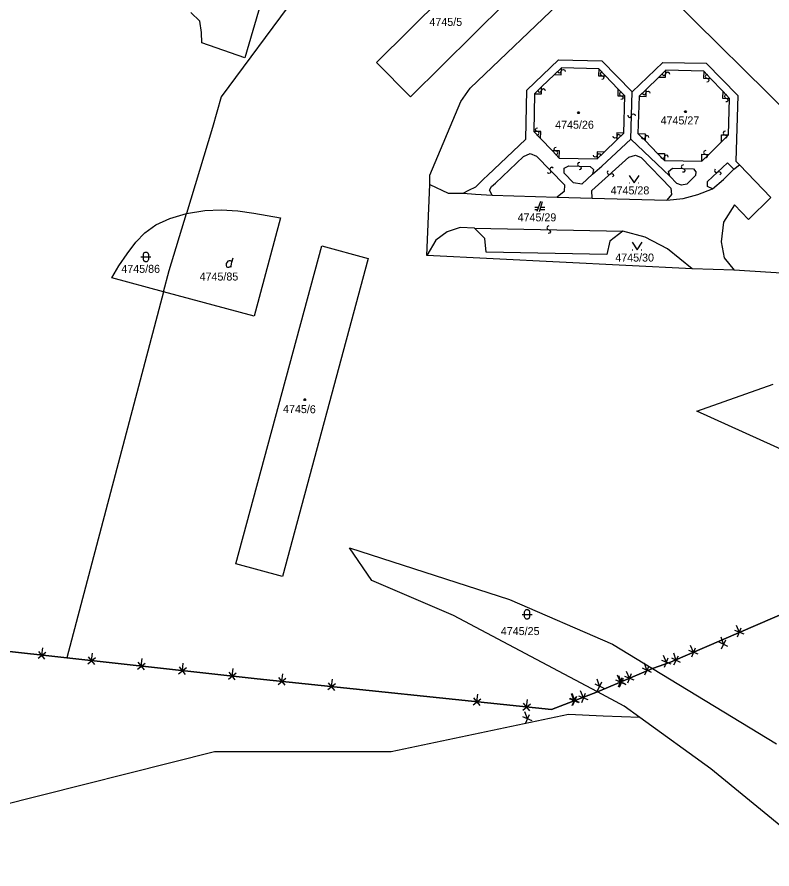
# Model space of a CAD drawing. Extents: x -266179 to -264727, y -1243225 to -1241702.
# Drawn here: x -265475.1 to -265324.1, y -1242256.8 to -1242086.5 of the extents above; entities that cross this region are included whole.
import ezdxf

# ---------------------------------------------------------------- set-up
doc = ezdxf.new("R2010")
doc.units = 0
for name, color, linetype in [('Vrstva 1', 7, 'Continuous'), ('Vrstva 2', 7, 'Continuous'), ('Vrstva 21', 7, 'Continuous')]:
    doc.layers.add(name, color=color, linetype=linetype)

msp = doc.modelspace()

# ---------------------------------------------------------------- linework, layer by layer
at = {"layer": 'Vrstva 1'}
for p, q in [((-265367.1, -1242011.91), (-265434.24, -1242102.45)), ((-265374.2, -1242053.02), (-265286.2, -1242140.05)), ((-265419.94, -1242061.77), (-265429.51, -1242094.71)), ((-265403.16, -1242095.63), (-265379.52, -1242072.17)), ((-265384.47, -1242100.74), (-265365.02, -1242082.22)), ((-265377.37, -1242083.7), (-265396.35, -1242102.47)), ((-265438.52, -1242087.33), (-265440.29, -1242085.63)), ((-265438.2, -1242089.6), (-265438.52, -1242087.33)), ((-265438.09, -1242091.7), (-265438.2, -1242089.6)), ((-265429.51, -1242094.71), (-265438.09, -1242091.7)), ((-265373.08, -1242101.16), (-265366.78, -1242095.08)), ((-265366.78, -1242095.08), (-265358.12, -1242095.29)), ((-265358.12, -1242095.29), (-265352.07, -1242101.46)), ((-265396.35, -1242102.47), (-265403.16, -1242095.63)), ((-265366.17, -1242096.65), (-265367.57, -1242098)), ((-265358.73, -1242096.86), (-265366.17, -1242096.65)), ((-265357.38, -1242098.27), (-265358.73, -1242096.86)), ((-265352.07, -1242101.46), (-265345.93, -1242095.64)), ((-265345.93, -1242095.64), (-265337.25, -1242095.78)), ((-265337.25, -1242095.78), (-265330.93, -1242102.23)), ((-265367.57, -1242098), (-265370.16, -1242100.5)), ((-265354.88, -1242100.88), (-265357.38, -1242098.27)), ((-265346.7, -1242098.52), (-265349.27, -1242100.99)), ((-265345.3, -1242097.16), (-265346.7, -1242098.52)), ((-265337.7, -1242097.37), (-265345.3, -1242097.16)), ((-265336.35, -1242098.78), (-265337.7, -1242097.37)), ((-265333.89, -1242101.37), (-265336.35, -1242098.78)), ((-265386.31, -1242103.38), (-265384.47, -1242100.74)), ((-265373.32, -1242110.96), (-265373.08, -1242101.16)), ((-265371.56, -1242101.85), (-265371.73, -1242109.38)), ((-265370.16, -1242100.5), (-265371.56, -1242101.85)), ((-265353.53, -1242102.29), (-265354.88, -1242100.88)), ((-265349.27, -1242100.99), (-265350.67, -1242102.35)), ((-265332.54, -1242102.78), (-265333.89, -1242101.37)), ((-265434.24, -1242102.45), (-265435.97, -1242108.6)), ((-265392.48, -1242118.16), (-265386.31, -1242103.38)), ((-265353.69, -1242109.72), (-265353.53, -1242102.29)), ((-265350.67, -1242102.35), (-265350.91, -1242109.84)), ((-265332.76, -1242110.1), (-265332.54, -1242102.78)), ((-265330.93, -1242102.23), (-265331.31, -1242115.32)), ((-265435.97, -1242108.6), (-265441.2, -1242125.8)), ((-265371.73, -1242109.38), (-265370.38, -1242110.79)), ((-265355.09, -1242111.07), (-265353.69, -1242109.72)), ((-265350.91, -1242109.84), (-265349.45, -1242111.23)), ((-265334.15, -1242111.46), (-265332.76, -1242110.1)), ((-265380.94, -1242118.21), (-265373.32, -1242110.96)), ((-265370.38, -1242110.79), (-265367.97, -1242113.3)), ((-265357.66, -1242113.55), (-265355.09, -1242111.07)), ((-265349.45, -1242111.23), (-265346.95, -1242113.79)), ((-265336.72, -1242113.98), (-265334.15, -1242111.46)), ((-265367.97, -1242113.3), (-265366.62, -1242114.71)), ((-265359.06, -1242114.9), (-265357.66, -1242113.55)), ((-265346.95, -1242113.79), (-265345.59, -1242115.18)), ((-265338.11, -1242115.34), (-265336.72, -1242113.98)), ((-265366.62, -1242114.71), (-265359.06, -1242114.9)), ((-265345.59, -1242115.18), (-265338.11, -1242115.34)), ((-265331.31, -1242115.32), (-265330.54, -1242116.06)), ((-265333.76, -1242119.02), (-265331.67, -1242116.91)), ((-265331.67, -1242116.91), (-265330.54, -1242116.06)), ((-265330.54, -1242116.06), (-265324.31, -1242122.59)), ((-265392.53, -1242119.97), (-265392.48, -1242118.16)), ((-265383.33, -1242120.45), (-265381.72, -1242118.9)), ((-265381.72, -1242118.9), (-265380.94, -1242118.21)), ((-265335.98, -1242120.89), (-265333.76, -1242119.02)), ((-265393.12, -1242134.22), (-265392.53, -1242119.97)), ((-265392.53, -1242119.97), (-265388.87, -1242121.71)), ((-265384.7, -1242121.16), (-265383.33, -1242120.45)), ((-265352.59, -1242119.7), (-265352.49, -1242119.7)), ((-265350.79, -1242119.7), (-265350.69, -1242119.7)), ((-265338.92, -1242122.03), (-265335.98, -1242120.89)), ((-265388.87, -1242121.71), (-265385.85, -1242121.75)), ((-265385.85, -1242121.75), (-265384.7, -1242121.16)), ((-265385.85, -1242121.75), (-265383.34, -1242121.93)), ((-265383.34, -1242121.93), (-265380.06, -1242122.16)), ((-265380.06, -1242122.16), (-265367.07, -1242122.51)), ((-265367.07, -1242122.51), (-265360.04, -1242122.76)), ((-265341.82, -1242122.78), (-265338.92, -1242122.03)), ((-265324.31, -1242122.59), (-265328.79, -1242127)), ((-265370.39, -1242123.38), (-265371.09, -1242125.38)), ((-265370.59, -1242125.38), (-265369.99, -1242123.38)), ((-265360.04, -1242122.76), (-265345.1, -1242123.13)), ((-265345.1, -1242123.13), (-265341.82, -1242122.78)), ((-265331.56, -1242124.04), (-265333.8, -1242127.51)), ((-265328.79, -1242127), (-265331.56, -1242124.04)), ((-265444.66, -1242137.17), (-265441.2, -1242125.8)), ((-265444.52, -1242126.77), (-265441.2, -1242125.8)), ((-265441.2, -1242125.8), (-265437.5, -1242125.2)), ((-265437.5, -1242125.2), (-265434.27, -1242125.06)), ((-265434.27, -1242125.06), (-265430.89, -1242125.27)), ((-265430.89, -1242125.27), (-265427.68, -1242125.76)), ((-265427.68, -1242125.76), (-265422.36, -1242126.68)), ((-265370.81, -1242124.58), (-265371.49, -1242124.58)), ((-265371.49, -1242124.98), (-265370.95, -1242124.98)), ((-265370.47, -1242124.98), (-265369.49, -1242124.98)), ((-265369.49, -1242124.58), (-265370.35, -1242124.58)), ((-265447.32, -1242128.09), (-265444.52, -1242126.77)), ((-265422.36, -1242126.68), (-265427.66, -1242146.32)), ((-265333.8, -1242127.51), (-265334.21, -1242131.45)), ((-265449.5, -1242129.69), (-265447.32, -1242128.09)), ((-265389.04, -1242129.43), (-265391.28, -1242131.12)), ((-265386.42, -1242128.58), (-265389.04, -1242129.43)), ((-265383.57, -1242128.73), (-265386.42, -1242128.58)), ((-265383.07, -1242129.24), (-265383.57, -1242128.73)), ((-265381.52, -1242130.79), (-265383.07, -1242129.24)), ((-265353.91, -1242129.34), (-265356.52, -1242131.3)), ((-265349.47, -1242130.56), (-265353.91, -1242129.34)), ((-265451.29, -1242131.56), (-265449.5, -1242129.69)), ((-265391.28, -1242131.12), (-265393.12, -1242134.22)), ((-265381.21, -1242133.54), (-265381.52, -1242130.79)), ((-265344.99, -1242132.88), (-265349.47, -1242130.56)), ((-265453.01, -1242133.89), (-265451.29, -1242131.56)), ((-265431.28, -1242195.85), (-265414.11, -1242132.25)), ((-265414.11, -1242132.25), (-265404.81, -1242134.79)), ((-265356.52, -1242131.3), (-265357.08, -1242134)), ((-265334.21, -1242131.45), (-265333.65, -1242134.64)), ((-265454.68, -1242136.27), (-265453.01, -1242133.89)), ((-265340.06, -1242136.83), (-265393.12, -1242134.22)), ((-265357.08, -1242134), (-265381.21, -1242133.54)), ((-265352.01, -1242133.04), (-265351.91, -1242133.04)), ((-265350.21, -1242133.04), (-265350.11, -1242133.04)), ((-265340.06, -1242136.83), (-265344.99, -1242132.88)), ((-265432.08, -1242135.53), (-265431.81, -1242134.63)), ((-265404.81, -1242134.79), (-265421.96, -1242198.37)), ((-265333.65, -1242134.64), (-265331.61, -1242137.1)), ((-265456.14, -1242138.63), (-265454.68, -1242136.27)), ((-265445.78, -1242141.43), (-265444.66, -1242137.17)), ((-265331.61, -1242137.1), (-265340.06, -1242136.83)), ((-265286.2, -1242140.05), (-265331.61, -1242137.1)), ((-265445.78, -1242141.43), (-265456.14, -1242138.63)), ((-265445.78, -1242141.43), (-265465.13, -1242214.65)), ((-265427.66, -1242146.32), (-265445.78, -1242141.43)), ((-265339.07, -1242165.29), (-265323.84, -1242159.92)), ((-265319.39, -1242174.23), (-265339.07, -1242165.29)), ((-265344.34, -1242215.5), (-265286.21, -1242190.26)), ((-265404.11, -1242199.16), (-265408.59, -1242192.62)), ((-265408.59, -1242192.62), (-265376.56, -1242202.94)), ((-265421.96, -1242198.37), (-265431.28, -1242195.85)), ((-265387.78, -1242206.14), (-265404.11, -1242199.16)), ((-265376.56, -1242202.94), (-265355.95, -1242211.88)), ((-265358.97, -1242221.43), (-265387.78, -1242206.14)), ((-265526.22, -1242207.84), (-265465.13, -1242214.65)), ((-265355.95, -1242211.88), (-265347.97, -1242216.73)), ((-265465.13, -1242214.65), (-265427.06, -1242218.79)), ((-265347.97, -1242216.73), (-265344.34, -1242215.5)), ((-265347.97, -1242216.73), (-265358.97, -1242221.43)), ((-265347.97, -1242216.73), (-265323.18, -1242231.82)), ((-265427.06, -1242218.79), (-265368.17, -1242224.97)), ((-265368.17, -1242224.97), (-265358.97, -1242221.43)), ((-265353.62, -1242224.28), (-265358.97, -1242221.43)), ((-265350.5, -1242226.57), (-265353.62, -1242224.28)), ((-265364.78, -1242225.97), (-265400.24, -1242233.42)), ((-265357.82, -1242226.28), (-265364.78, -1242225.97)), ((-265350.5, -1242226.57), (-265357.82, -1242226.28)), ((-265336.29, -1242236.79), (-265350.5, -1242226.57)), ((-265435.54, -1242233.42), (-265498.59, -1242249.25)), ((-265400.24, -1242233.42), (-265435.54, -1242233.42)), ((-265311.93, -1242256.82), (-265336.29, -1242236.79))]:
    msp.add_line(p, q, dxfattribs=at)
for points in [[(-265362.69, -1242105.49), (-265362.6, -1242105.64), (-265362.69, -1242105.79), (-265362.87, -1242105.79), (-265362.96, -1242105.64), (-265362.87, -1242105.49)], [(-265341.29, -1242105.29), (-265341.2, -1242105.44), (-265341.29, -1242105.59), (-265341.47, -1242105.59), (-265341.56, -1242105.44), (-265341.47, -1242105.29)], [(-265449.8, -1242133.98), (-265449.7, -1242133.69), (-265449.45, -1242133.51), (-265449.14, -1242133.51), (-265448.89, -1242133.69), (-265448.79, -1242133.98), (-265448.79, -1242134.98), (-265448.89, -1242135.27), (-265449.14, -1242135.45), (-265449.45, -1242135.45), (-265449.7, -1242135.27), (-265449.8, -1242134.98)], [(-265417.42, -1242162.85), (-265417.33, -1242163), (-265417.42, -1242163.15), (-265417.6, -1242163.15), (-265417.69, -1242163), (-265417.6, -1242162.85)], [(-265373.56, -1242205.43), (-265373.46, -1242205.14), (-265373.21, -1242204.96), (-265372.9, -1242204.96), (-265372.65, -1242205.14), (-265372.55, -1242205.43), (-265372.55, -1242206.43), (-265372.65, -1242206.72), (-265372.9, -1242206.9), (-265373.21, -1242206.9), (-265373.46, -1242206.72), (-265373.56, -1242206.43)]]:
    msp.add_lwpolyline(points, close=True, dxfattribs=at)
for points in [[(-265352.64, -1242118.2), (-265351.64, -1242119.7), (-265350.64, -1242118.2)], [(-265352.06, -1242131.54), (-265351.06, -1242133.04), (-265350.06, -1242131.54)], [(-265450.3, -1242134.48), (-265449.03, -1242134.48), (-265448.3, -1242134.48)], [(-265432.26, -1242136.52), (-265432.26, -1242136.25), (-265432.08, -1242135.53), (-265432.17, -1242135.35), (-265432.35, -1242135.26), (-265432.62, -1242135.26), (-265432.89, -1242135.35), (-265433.07, -1242135.53), (-265433.25, -1242135.8), (-265433.25, -1242136.16), (-265433.16, -1242136.43), (-265432.98, -1242136.52), (-265432.71, -1242136.52), (-265432.53, -1242136.43), (-265432.26, -1242136.25)], [(-265374.06, -1242205.93), (-265372.79, -1242205.93), (-265372.06, -1242205.93)]]:
    msp.add_lwpolyline(points, dxfattribs=at)
at = {"layer": 'Vrstva 2'}
for p, q in [((-265366.21, -1242098.05), (-265366.17, -1242096.65)), ((-265358.73, -1242096.86), (-265358.77, -1242098.26)), ((-265367.57, -1242098), (-265366.21, -1242098.05)), ((-265358.77, -1242098.26), (-265357.38, -1242098.27)), ((-265346.7, -1242098.52), (-265345.34, -1242098.56)), ((-265345.34, -1242098.56), (-265345.3, -1242097.16)), ((-265337.7, -1242097.37), (-265337.74, -1242098.77)), ((-265337.74, -1242098.77), (-265336.35, -1242098.78)), ((-265371.56, -1242101.85), (-265370.16, -1242101.88)), ((-265370.16, -1242101.88), (-265370.16, -1242100.5)), ((-265354.88, -1242100.88), (-265354.93, -1242102.26)), ((-265352.3, -1242110.97), (-265352.07, -1242101.46)), ((-265349.27, -1242102.38), (-265349.27, -1242100.99)), ((-265333.89, -1242101.37), (-265333.94, -1242102.74)), ((-265354.93, -1242102.26), (-265353.53, -1242102.29)), ((-265350.67, -1242102.35), (-265349.27, -1242102.38)), ((-265333.94, -1242102.74), (-265332.54, -1242102.78)), ((-265370.33, -1242109.41), (-265371.73, -1242109.38)), ((-265370.38, -1242110.79), (-265370.33, -1242109.41)), ((-265353.69, -1242109.72), (-265355.09, -1242109.69)), ((-265355.09, -1242109.69), (-265355.09, -1242111.07)), ((-265350.91, -1242109.84), (-265349.41, -1242109.87)), ((-265349.41, -1242109.87), (-265349.45, -1242111.23)), ((-265334.15, -1242111.46), (-265334.16, -1242110.06)), ((-265334.16, -1242110.06), (-265332.76, -1242110.1)), ((-265358.12, -1242116.35), (-265352.3, -1242110.97)), ((-265352.3, -1242110.97), (-265344.51, -1242118.36)), ((-265373.79, -1242114.4), (-265372.47, -1242113.82)), ((-265372.47, -1242113.82), (-265371.18, -1242114.32)), ((-265366.58, -1242113.3), (-265367.97, -1242113.3)), ((-265366.62, -1242114.71), (-265366.58, -1242113.3)), ((-265359.02, -1242113.5), (-265359.06, -1242114.9)), ((-265357.66, -1242113.55), (-265359.02, -1242113.5)), ((-265346.95, -1242113.79), (-265345.56, -1242113.78)), ((-265345.56, -1242113.78), (-265345.59, -1242115.18)), ((-265338.11, -1242115.34), (-265338.08, -1242113.94)), ((-265338.08, -1242113.94), (-265336.72, -1242113.98)), ((-265379.35, -1242119.72), (-265373.79, -1242114.4)), ((-265371.18, -1242114.32), (-265365.59, -1242120.07)), ((-265360.09, -1242121.22), (-265352.72, -1242114.55)), ((-265352.72, -1242114.55), (-265351.35, -1242114.13)), ((-265351.35, -1242114.13), (-265350.26, -1242114.63)), ((-265350.26, -1242114.63), (-265344.32, -1242120.75)), ((-265336.95, -1242119.37), (-265332.94, -1242115.66)), ((-265332.94, -1242115.66), (-265331.67, -1242116.91)), ((-265365.65, -1242116.75), (-265364.72, -1242116.29)), ((-265365.63, -1242117.74), (-265365.65, -1242116.75)), ((-265364.72, -1242116.29), (-265360.47, -1242116.41)), ((-265360.47, -1242116.41), (-265359.75, -1242117.03)), ((-265359.94, -1242117.96), (-265358.12, -1242116.35)), ((-265359.75, -1242117.03), (-265359.94, -1242117.96)), ((-265344.76, -1242117.43), (-265343.97, -1242116.74)), ((-265344.51, -1242118.36), (-265344.76, -1242117.43)), ((-265343.97, -1242116.74), (-265339.75, -1242116.9)), ((-265339.75, -1242116.9), (-265339.32, -1242117.46)), ((-265339.32, -1242117.46), (-265339.34, -1242118.22)), ((-265363.8, -1242119.67), (-265365.63, -1242117.74)), ((-265359.94, -1242117.96), (-265362.11, -1242119.95)), ((-265343.09, -1242119.79), (-265344.51, -1242118.36)), ((-265339.34, -1242118.22), (-265341.11, -1242119.95)), ((-265380.54, -1242121.15), (-265380.15, -1242120.4)), ((-265380.15, -1242120.4), (-265379.35, -1242119.72)), ((-265365.59, -1242120.07), (-265365.65, -1242121.38)), ((-265362.11, -1242119.95), (-265363.8, -1242119.67)), ((-265344.32, -1242120.75), (-265344.16, -1242122)), ((-265342.16, -1242120.11), (-265343.09, -1242119.79)), ((-265341.11, -1242119.95), (-265342.16, -1242120.11)), ((-265336.95, -1242120.38), (-265336.95, -1242119.37)), ((-265335.98, -1242120.89), (-265336.95, -1242120.38)), ((-265380.06, -1242122.16), (-265380.54, -1242121.15)), ((-265365.65, -1242121.38), (-265367.07, -1242122.51)), ((-265360.04, -1242122.76), (-265360.09, -1242121.22)), ((-265344.16, -1242122), (-265345.1, -1242123.13)), ((-265383.57, -1242128.73), (-265353.91, -1242129.34))]:
    msp.add_line(p, q, dxfattribs=at)
for points in [[(-265366.938, -1242097.278), (-265366.837, -1242097.591), (-265366.541, -1242097.71), (-265366.287, -1242097.577), (-265366.072, -1242097.083), (-265365.77, -1242096.992), (-265365.504, -1242097.16), (-265365.442, -1242097.422)], [(-265358.02, -1242097.515), (-265358.33, -1242097.623), (-265358.443, -1242097.922), (-265358.304, -1242098.173), (-265357.806, -1242098.377), (-265357.708, -1242098.678), (-265357.87, -1242098.946), (-265358.13, -1242099.015)], [(-265346.068, -1242097.788), (-265345.967, -1242098.101), (-265345.671, -1242098.22), (-265345.417, -1242098.087), (-265345.202, -1242097.593), (-265344.9, -1242097.502), (-265344.634, -1242097.67), (-265344.572, -1242097.932)], [(-265336.99, -1242098.025), (-265337.3, -1242098.133), (-265337.413, -1242098.432), (-265337.274, -1242098.683), (-265336.776, -1242098.887), (-265336.678, -1242099.188), (-265336.84, -1242099.456), (-265337.1, -1242099.525)], [(-265370.91, -1242101.14), (-265370.8, -1242101.45), (-265370.5, -1242101.56), (-265370.25, -1242101.42), (-265370.05, -1242100.92), (-265369.75, -1242100.82), (-265369.48, -1242100.98), (-265369.41, -1242101.24)], [(-265354.164, -1242101.526), (-265354.476, -1242101.63), (-265354.593, -1242101.927), (-265354.458, -1242102.18), (-265353.962, -1242102.391), (-265353.869, -1242102.693), (-265354.034, -1242102.959), (-265354.296, -1242103.024)], [(-265350.02, -1242101.635), (-265349.91, -1242101.945), (-265349.61, -1242102.055), (-265349.36, -1242101.915), (-265349.16, -1242101.415), (-265348.86, -1242101.315), (-265348.59, -1242101.475), (-265348.52, -1242101.735)], [(-265333.169, -1242102.012), (-265333.482, -1242102.113), (-265333.6, -1242102.41), (-265333.467, -1242102.664), (-265332.973, -1242102.878), (-265332.882, -1242103.18), (-265333.049, -1242103.446), (-265333.311, -1242103.508)], [(-265352.934, -1242106.147), (-265352.831, -1242106.46), (-265352.534, -1242106.577), (-265352.28, -1242106.443), (-265352.069, -1242105.948), (-265351.766, -1242105.855), (-265351.5, -1242106.021), (-265351.436, -1242106.283)], [(-265371.096, -1242110.144), (-265370.784, -1242110.04), (-265370.667, -1242109.743), (-265370.802, -1242109.49), (-265371.298, -1242109.279), (-265371.391, -1242108.977), (-265371.225, -1242108.711), (-265370.964, -1242108.646)], [(-265354.34, -1242110.43), (-265354.45, -1242110.12), (-265354.75, -1242110.01), (-265355, -1242110.15), (-265355.2, -1242110.65), (-265355.5, -1242110.75), (-265355.77, -1242110.59), (-265355.84, -1242110.33)], [(-265348.682, -1242110.622), (-265348.783, -1242110.309), (-265349.079, -1242110.19), (-265349.333, -1242110.323), (-265349.548, -1242110.817), (-265349.851, -1242110.908), (-265350.116, -1242110.74), (-265350.178, -1242110.478)], [(-265333.389, -1242109.332), (-265333.702, -1242109.433), (-265333.82, -1242109.73), (-265333.687, -1242109.984), (-265333.193, -1242110.198), (-265333.102, -1242110.5), (-265333.269, -1242110.766), (-265333.531, -1242110.828)], [(-265367.325, -1242114.05), (-265367.015, -1242113.94), (-265366.905, -1242113.64), (-265367.045, -1242113.39), (-265367.545, -1242113.19), (-265367.645, -1242112.89), (-265367.485, -1242112.62), (-265367.225, -1242112.55)], [(-265358.292, -1242114.271), (-265358.393, -1242113.958), (-265358.69, -1242113.84), (-265358.944, -1242113.973), (-265359.158, -1242114.467), (-265359.46, -1242114.558), (-265359.726, -1242114.391), (-265359.788, -1242114.129)], [(-265337.328, -1242113.212), (-265337.641, -1242113.313), (-265337.76, -1242113.609), (-265337.627, -1242113.863), (-265337.133, -1242114.078), (-265337.042, -1242114.381), (-265337.21, -1242114.646), (-265337.472, -1242114.708)], [(-265362.524, -1242115.602), (-265362.837, -1242115.703), (-265362.955, -1242116), (-265362.822, -1242116.254), (-265362.328, -1242116.468), (-265362.237, -1242116.77), (-265362.404, -1242117.036), (-265362.666, -1242117.098)], [(-265344.826, -1242114.546), (-265344.93, -1242114.234), (-265345.227, -1242114.117), (-265345.48, -1242114.252), (-265345.691, -1242114.748), (-265345.993, -1242114.841), (-265346.259, -1242114.675), (-265346.324, -1242114.414)], [(-265367.813, -1242116.708), (-265368.108, -1242116.562), (-265368.399, -1242116.693), (-265368.481, -1242116.967), (-265368.276, -1242117.465), (-265368.421, -1242117.746), (-265368.726, -1242117.82), (-265368.957, -1242117.682)], [(-265356.871, -1242117.296), (-265357.027, -1242117.585), (-265356.907, -1242117.881), (-265356.636, -1242117.973), (-265356.131, -1242117.785), (-265355.856, -1242117.94), (-265355.793, -1242118.248), (-265355.939, -1242118.474)], [(-265341.781, -1242116.072), (-265342.095, -1242116.171), (-265342.217, -1242116.466), (-265342.086, -1242116.721), (-265341.594, -1242116.94), (-265341.506, -1242117.244), (-265341.676, -1242117.508), (-265341.939, -1242117.568)], [(-265335.418, -1242116.931), (-265335.571, -1242117.222), (-265335.447, -1242117.517), (-265335.175, -1242117.605), (-265334.672, -1242117.412), (-265334.395, -1242117.564), (-265334.329, -1242117.871), (-265334.472, -1242118.099)], [(-265368.675, -1242128.286), (-265368.987, -1242128.39), (-265369.103, -1242128.688), (-265368.968, -1242128.94), (-265368.472, -1242129.15), (-265368.378, -1242129.452), (-265368.544, -1242129.719), (-265368.805, -1242129.784)]]:
    msp.add_lwpolyline(points, dxfattribs=at)
at = {"layer": 'Vrstva 21'}
for p, q in [((-265344.34, -1242215.5), (-265286.21, -1242190.26)), ((-265286.21, -1242190.26), (-265344.34, -1242215.5)), ((-265526.22, -1242207.84), (-265465.13, -1242214.65)), ((-265465.13, -1242214.65), (-265526.22, -1242207.84)), ((-265329.66, -1242209.89), (-265331.501, -1242209.163)), ((-265330.581, -1242209.527), (-265331.178, -1242208.151)), ((-265330.944, -1242210.448), (-265330.217, -1242208.606)), ((-265333.763, -1242211.918), (-265334.244, -1242210.497)), ((-265334.202, -1242212.805), (-265333.324, -1242211.03)), ((-265470.099, -1242214.094), (-265469.933, -1242212.603)), ((-265339.754, -1242213.508), (-265340.351, -1242212.132)), ((-265340.118, -1242214.428), (-265339.391, -1242212.587)), ((-265332.875, -1242212.356), (-265334.65, -1242211.479)), ((-265470.872, -1242214.712), (-265469.326, -1242213.475)), ((-265469.481, -1242214.867), (-265470.717, -1242213.321)), ((-265460.931, -1242215.809), (-265459.387, -1242214.569)), ((-265459.539, -1242215.961), (-265460.779, -1242214.417)), ((-265460.159, -1242215.189), (-265459.997, -1242213.698)), ((-265345.176, -1242215.538), (-265345.764, -1242214.159)), ((-265343.235, -1242215.124), (-265343.716, -1242213.703)), ((-265343.674, -1242216.011), (-265342.796, -1242214.237)), ((-265338.833, -1242213.871), (-265340.675, -1242213.144)), ((-265465.13, -1242214.65), (-265427.06, -1242218.79)), ((-265427.06, -1242218.79), (-265465.13, -1242214.65)), ((-265450.99, -1242216.893), (-265449.446, -1242215.653)), ((-265449.598, -1242217.045), (-265450.838, -1242215.501)), ((-265450.218, -1242216.273), (-265450.055, -1242214.782)), ((-265441.972, -1242217.167), (-265441.809, -1242215.676)), ((-265349.075, -1242217.106), (-265349.556, -1242215.685)), ((-265349.514, -1242217.993), (-265348.636, -1242216.219)), ((-265347.97, -1242216.73), (-265344.34, -1242215.5)), ((-265344.34, -1242215.5), (-265347.97, -1242216.73)), ((-265344.257, -1242215.907), (-265346.094, -1242215.169)), ((-265345.545, -1242216.457), (-265344.807, -1242214.62)), ((-265342.347, -1242215.563), (-265344.122, -1242214.685)), ((-265442.744, -1242217.787), (-265441.2, -1242216.547)), ((-265441.352, -1242217.939), (-265442.592, -1242216.395)), ((-265432.803, -1242218.871), (-265431.259, -1242217.631)), ((-265431.411, -1242219.023), (-265432.651, -1242217.479)), ((-265432.031, -1242218.251), (-265431.868, -1242216.76)), ((-265422.087, -1242219.312), (-265421.931, -1242217.82)), ((-265358.97, -1242221.43), (-265347.97, -1242216.73)), ((-265347.97, -1242216.73), (-265358.97, -1242221.43)), ((-265352.567, -1242218.696), (-265353.156, -1242217.317)), ((-265352.936, -1242219.615), (-265352.198, -1242217.778)), ((-265348.188, -1242217.545), (-265349.963, -1242216.667)), ((-265427.06, -1242218.79), (-265368.17, -1242224.97)), ((-265368.17, -1242224.97), (-265427.06, -1242218.79)), ((-265422.857, -1242219.935), (-265421.318, -1242218.689)), ((-265421.464, -1242220.081), (-265422.71, -1242218.542)), ((-265411.519, -1242221.125), (-265412.765, -1242219.586)), ((-265412.142, -1242220.356), (-265411.985, -1242218.864)), ((-265358.547, -1242220.312), (-265359.028, -1242218.892)), ((-265358.986, -1242221.2), (-265358.108, -1242219.425)), ((-265353.454, -1242219.833), (-265355.291, -1242219.095)), ((-265353.266, -1242219.985), (-265355.075, -1242219.181)), ((-265354.373, -1242219.464), (-265354.962, -1242218.084)), ((-265354.742, -1242220.382), (-265354.004, -1242218.545)), ((-265354.171, -1242219.583), (-265354.71, -1242218.183)), ((-265354.573, -1242220.488), (-265353.769, -1242218.678)), ((-265351.649, -1242219.065), (-265353.486, -1242218.327)), ((-265412.911, -1242220.979), (-265411.373, -1242219.733)), ((-265361.764, -1242222.622), (-265362.353, -1242221.242)), ((-265357.66, -1242220.751), (-265359.435, -1242219.874)), ((-265383.857, -1242224.027), (-265382.319, -1242222.781)), ((-265382.465, -1242224.174), (-265383.711, -1242222.635)), ((-265383.088, -1242223.404), (-265382.931, -1242221.913)), ((-265373.143, -1242224.448), (-265372.986, -1242222.957)), ((-265368.17, -1242224.97), (-265358.97, -1242221.43)), ((-265358.97, -1242221.43), (-265368.17, -1242224.97)), ((-265362.732, -1242223.627), (-265364.541, -1242222.823)), ((-265362.599, -1242223.577), (-265364.408, -1242222.773)), ((-265363.637, -1242223.225), (-265364.175, -1242221.825)), ((-265363.503, -1242223.175), (-265364.042, -1242221.775)), ((-265364.038, -1242224.13), (-265363.235, -1242222.32)), ((-265363.905, -1242224.08), (-265363.102, -1242222.27)), ((-265360.846, -1242222.991), (-265362.683, -1242222.253)), ((-265362.133, -1242223.54), (-265361.395, -1242221.703)), ((-265373.912, -1242225.071), (-265372.373, -1242223.825)), ((-265372.52, -1242225.218), (-265373.766, -1242223.679)), ((-265372.065, -1242227.219), (-265373.874, -1242226.415)), ((-265372.969, -1242226.817), (-265373.508, -1242225.417)), ((-265373.371, -1242227.722), (-265372.567, -1242225.912))]:
    msp.add_line(p, q, dxfattribs=at)

# ---------------------------------------------------------------- texts
at = {"layer": 'Vrstva 1'}
for s, p in [('4745/5', (-265392.583, -1242088.3)), ('4745/26', (-265367.435, -1242108.85)), ('4745/27', (-265346.351, -1242107.99)), ('4745/28', (-265356.341, -1242121.98)), ('4745/29', (-265374.948, -1242127.37)), ('4745/30', (-265355.41, -1242135.41)), ('4745/86', (-265454.205, -1242137.66)), ('4745/85', (-265438.551, -1242139.2)), ('4745/25', (-265378.301, -1242210.07))]:
    msp.add_text(s, height=1.6, dxfattribs=at).set_placement(p)
msp.add_text('4745/6', height=1.6, rotation=359.07265, dxfattribs=at).set_placement((-265421.873, -1242165.633))

doc.saveas('drawing.dxf')
